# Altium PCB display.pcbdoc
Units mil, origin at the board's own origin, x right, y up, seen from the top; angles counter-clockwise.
Board outline 7440.31 x 2415 mil, 2 copper layers (Top Layer, Bottom Layer); 54 components, 78 nets, 200 pads, 151 vias.
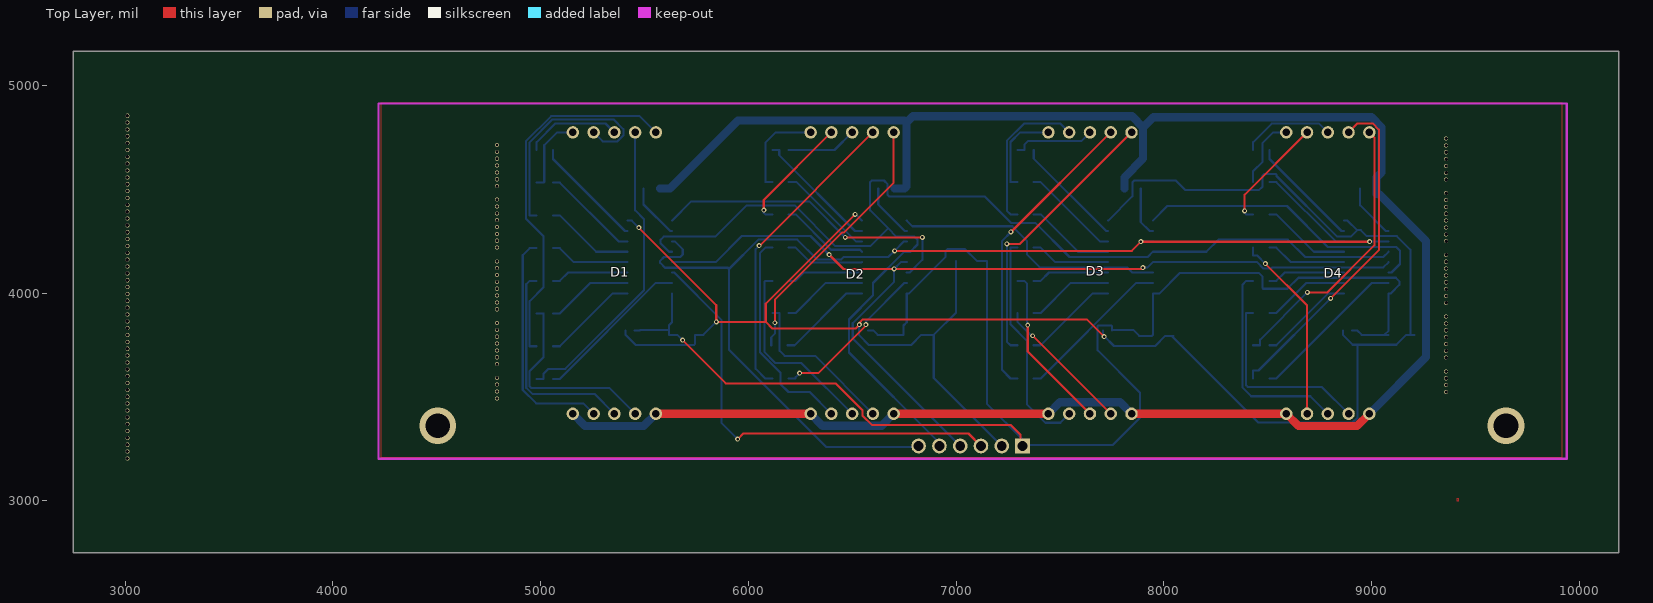
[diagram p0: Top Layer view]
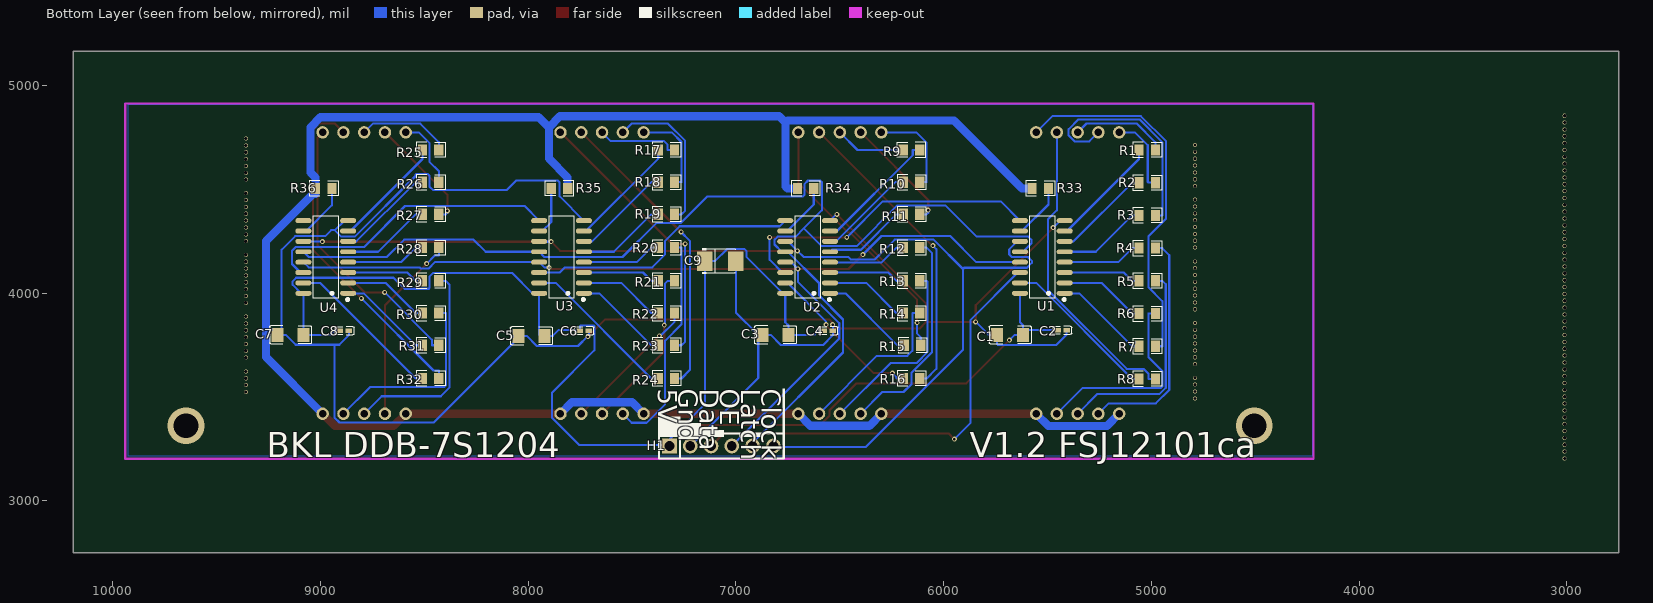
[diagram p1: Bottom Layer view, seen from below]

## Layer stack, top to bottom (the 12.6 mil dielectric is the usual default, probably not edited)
Top Layer: signal copper (thickness not stored)
Dielectric: dielectric 12.6, FR-4, Dk 4.8
Bottom Layer: signal copper (thickness not stored)

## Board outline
10190.31,2750 2750,2750 2750,5165 10190.31,5165

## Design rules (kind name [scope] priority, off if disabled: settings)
Clearance safeClearance [All] p1: gap=7 ignorepadtopadclearanceinfootprint=FALSE except(6: Track-Track Track-SMDPad SMDPad-SMDPad Track-THPad SMDPad-THPad THPad-THPad Track-Via SMDPad-Via THPad-Via Via-Via Track-Fill SMDPad-Fill THPad-Fill Via-Fill Fill-Fill Track-Region SMDPad-Region THPad-Region Via-Region Fill-Region Region-Region Track-Poly SMDPad-Poly THPad-Poly Via-Poly Fill-Poly Region-Poly Poly-Poly Track-Text SMDPad-Text THPad-Text Via-Text Fill-Text Region-Text Poly-Text Text-Text Track-Hole SMDPad-Hole THPad-Hole Via-Hole Fill-Hole Region-Hole Poly-Hole Text-Hole; 11.8: Track-Sheet SMDPad-Sheet THPad-Sheet Via-Sheet Fill-Sheet Region-Sheet Poly-Sheet Text-Sheet Sheet-Hole)
DiffPairsRouting differentialPair [All] p1: maxuncoupledlength=10 minlimit=6 maxlimit=50 mostfreqgap=6 toplayer_minwidth=5 toplayer_prefwidth=10 toplayer_maxwidth=100 bottomlayer_minwidth=5 bottomlayer_prefwidth=10 bottomlayer_maxwidth=100
PasteMaskExpansion pasteMaskExpansion [All] p1:
PlaneConnect innerPlane [All] p1: planeconnectstyle=Relief reliefexpansion=20 reliefentries=4 reliefconductorwidth=10 reliefairgap=10
PolygonConnect copperRegion [All] p1: connectstyle=Relief reliefentries=4 reliefconductorwidth=10 polygonreliefangle="90 Angle" airgapwidth=10
RoutingVias viaSize [All] p1: viastyle="Through Hole" holewidth=12.0078 minholewidth=11.811 maxholewidth=236.2204 width=24.0158 minwidth=19.685 maxwidth=393.7008
SolderMaskExpansion solderMaskExpansion [All] p1: useseparateexpansions=TRUE expansion=2 expansionbottom=2
Width trackWidth [All] p1: maxlimit=100 minlimit=5 preferedwidth=10
Width Vcc [All] p1: maxlimit=100 minlimit=24 preferedwidth=39

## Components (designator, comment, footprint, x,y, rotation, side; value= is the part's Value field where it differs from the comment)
C1 "CL31A476MPHNNNE" C1206 5679.84,3800 r0 bottom
C2 "CL05B104KO5NNNC" C0402_NEW 5429.84,3821.36 r180 bottom
C3 "CL31A476MPHNNNE" C1206 6809.84,3800 r0 bottom
C4 "CL05B104KO5NNNC" C0402_NEW 6554.84,3820 r180 bottom
C5 "CL31A476MPHNNNE" C1206 7984.84,3795 r0 bottom
C6 "CL05B104KO5NNNC" C0402_NEW 7729.84,3820 r180 bottom
C7 "CL31A476MPHNNNE" C1206 9144.84,3800 r0 bottom
C8 "CL05B104KO5NNNC" C0402_NEW 8884.84,3820 r180 bottom
C9 "CA45-B-10V-100uF-M" CAP-SMD_L3.5-W2.8-R-RD 7074.84,4155 r0 bottom
D1 "FJS12101" FJS12101 5354.84,4100 r0 top
D2 "FJS12101" FJS12101 6499.84,4100 r0 top
D3 "FJS12101" FJS12101 7644.84,4100 r0 top
D4 "FJS12101" FJS12101 8789.84,4100 r0 top
H1 "PZ254R-11-06P" HDR-TH_6P-P2.54-V_Z-211-0611-0021-001 7069.84,3265 r180 bottom
R1 "0805W8F1000T5E_C17408" R0805 5019.84,4690 r0 bottom
R2 "0805W8F1000T5E_C17408" R0805 5019.84,4532.52 r0 bottom
R3 "0805W8F1000T5E_C17408" R0805 5019.84,4375.04 r0 bottom
R4 "0805W8F1000T5E_C17408" R0805 5019.84,4217.56 r0 bottom
R5 "0805W8F1000T5E_C17408" R0805 5019.84,4060.08 r0 bottom
R6 "0805W8F1000T5E_C17408" R0805 5019.84,3902.6 r0 bottom
R7 "0805W8F1000T5E_C17408" R0805 5019.84,3745.12 r0 bottom
R8 "0805W8F1000T5E_C17408" R0805 5019.84,3587.64 r0 bottom
R9 "0805W8F1000T5E_C17408" R0805 6154.84,4690 r180 bottom
R10 "0805W8F1000T5E_C17408" R0805 6154.84,4535 r0 bottom
R11 "0805W8F1000T5E_C17408" R0805 6154.84,4380 r0 bottom
R12 "0805W8F1000T5E_C17408" R0805 6154.84,4220 r0 bottom
R13 "0805W8F1000T5E_C17408" R0805 6154.84,4060 r0 bottom
R14 "0805W8F1000T5E_C17408" R0805 6154.84,3905 r0 bottom
R15 "0805W8F1000T5E_C17408" R0805 6149.84,3750 r0 bottom
R16 "0805W8F1000T5E_C17408" R0805 6154.84,3590 r0 bottom
R17 "0805W8F1000T5E_C17408" R0805 7334.84,4690 r0 bottom
R18 "0805W8F1000T5E_C17408" R0805 7334.84,4535 r0 bottom
R19 "0805W8F1000T5E_C17408" R0805 7334.84,4380 r0 bottom
R20 "0805W8F1000T5E_C17408" R0805 7334.84,4220 r0 bottom
R21 "0805W8F1000T5E_C17408" R0805 7334.84,4060 r0 bottom
R22 "0805W8F1000T5E_C17408" R0805 7334.84,3905 r0 bottom
R23 "0805W8F1000T5E_C17408" R0805 7334.84,3750 r0 bottom
R24 "0805W8F1000T5E_C17408" R0805 7334.84,3590 r0 bottom
R25 "0805W8F1000T5E_C17408" R0805 8469.84,4690 r0 bottom
R26 "0805W8F1000T5E_C17408" R0805 8469.84,4535 r0 bottom
R27 "0805W8F1000T5E_C17408" R0805 8469.84,4380 r0 bottom
R28 "0805W8F1000T5E_C17408" R0805 8469.84,4220 r0 bottom
R29 "0805W8F1000T5E_C17408" R0805 8469.84,4060 r0 bottom
R30 "0805W8F1000T5E_C17408" R0805 8469.84,3905 r0 bottom
R31 "0805W8F1000T5E_C17408" R0805 8469.84,3750 r0 bottom
R32 "0805W8F1000T5E_C17408" R0805 8469.84,3590 r0 bottom
R33 "0805W8F1002T5E" R0805 5534.84,4505 r0 bottom
R34 "0805W8F1002T5E" R0805 6664.84,4505 r0 bottom
R35 "0805W8F1002T5E" R0805 7849.84,4505 r180 bottom
R36 "0805W8F1002T5E" R0805 8984.84,4505 r0 bottom
U1 "={Manufacturer Part}" SOIC-16_L9.9-W3.9-P1.27-LS6.0-BL 5524.84,4175 r90 bottom
U2 "={Manufacturer Part}" SOIC-16_L9.9-W3.9-P1.27-LS6.0-BL 6654.84,4175 r90 bottom
U3 "={Manufacturer Part}" SOIC-16_L9.9-W3.9-P1.27-LS6.0-BL 7839.84,4175 r90 bottom
U4 "={Manufacturer Part}" SOIC-16_L9.9-W3.9-P1.27-LS6.0-BL 8974.84,4175 r90 bottom

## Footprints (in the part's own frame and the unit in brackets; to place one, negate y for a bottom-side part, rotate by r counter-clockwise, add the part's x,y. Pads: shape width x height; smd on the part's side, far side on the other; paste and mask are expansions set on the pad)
C0402_NEW [mm]
  rect 0.79x0.54 smd: 1(-0.545,0) 2(0.545,0)
  silkscreen extent -1.17,-0.5 1.17,0.5
C1206 [mm]
  rect 1.485x1.728 smd: 1(-1.593,0) 2(1.593,0)
  silkscreen extent -2.56,-1.09 2.56,1.09
CAP-SMD_L3.5-W2.8-R-RD [mm]
  rect 1.9x2.376 smd: 1(1.899,0) 2(-1.899,0)
  silkscreen extent -1.83,-1.55 2.21,1.55
FJS12101 [mil]
  round 60 hole 36: 1(-200,-680) 2(-100,-680) 3(0,-680) 4(100,-680) 5(200,-680) 6(200,675) 7(100,675) 8(0,675) 9(-100,675) 10(-200,675)
HDR-TH_6P-P2.54-V_Z-211-0611-0021-001 [mil]
  rect 70.9x70.9 hole 47.2: 1(-250,0)
  round 70.9 hole 47.2: 2(-150,0) 3(-50,0) 4(50,0) 5(150,0) 6(250,0)
  silkscreen extent -300,-60 300,60
R0805 [mm]
  rect 1.133x1.377 smd: 1(-1,0) 2(1,0)
  silkscreen extent -1.76,-0.92 1.76,0.92
SOIC-16_L9.9-W3.9-P1.27-LS6.0-BL [mil]
  oval 23.7x77.6 smd: 1(-175,-107.7) 2(-125,-107.7) 3(-75,-107.7) 4(-25,-107.7) 5(25,-107.7) 6(75,-107.7) 7(125,-107.7) 8(175,-107.7) 9(175,107.7) 10(125,107.7) 11(75,107.7) 12(25,107.7) 13(-25,107.7) 14(-75,107.7) 15(-125,107.7) 16(-175,107.7)
  silkscreen extent -211,-111 198,60

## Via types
v1: diameter 19.68, hole 15.75, Top Layer to Bottom Layer, 121 vias
v2: diameter 24, hole 12, Top Layer to Bottom Layer, 28 vias
v3: diameter 177.17, hole 118.11, Top Layer to Bottom Layer, 2 vias

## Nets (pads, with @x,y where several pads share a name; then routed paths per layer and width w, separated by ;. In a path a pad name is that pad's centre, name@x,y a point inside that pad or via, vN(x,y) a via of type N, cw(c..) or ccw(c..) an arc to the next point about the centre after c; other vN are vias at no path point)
$1N2297: U1.9 U2.14 | length 1524.5
  Top Layer w10: v2(6466.54,4268.7) v2(6838.14,4268.7)
  Bottom Layer w10: U1.9 5725.34,4442.8 6292.44,4442.8 v2(6466.54,4268.7) ; U2.14 6776.84,4100 6838.14,4161.3 v2(6838.14,4268.7)
$1N2299: R8.2 U1.15 | length 764.8
  Bottom Layer w10: R8.2 5092.54,3587.6 5554.94,4050 U1.15
$1N2301: R33.1 U1.10 | length 267.3
  Bottom Layer w10: R33.1@5495.44,4505 5495.44,4427.7 5623.14,4300 U1.10
$1N2302: H1.4 U1.13 U2.13 U3.13 U4.13 | length 4830.4
  Top Layer w10: v2(6388.54,4186.6) 6457.94,4117.2 v2(6701.54,4117.2) 7893.74,4117.2 v2(7899.94,4123.5)
  Bottom Layer w10: U1.13 5842.94,4150 5968.84,4276 6299.24,4276 v2(6388.54,4186.6) ; U2.13 6734.24,4150 v2(6701.54,4117.2) 6701.54,4055 6502.64,3856.2 6502.64,3782.2 H1.4 ; v2(7899.94,4123.5) 7921.04,4123.5 U3.13 8449.44,4150 8479.94,4119.5 8518.24,4119.5 8523.74,4125 9057.54,4125 U4.13
$1N2303: H1.5 U1.12 U2.12 U3.12 U4.12 | length 5880.5
  Bottom Layer w10: U1.12 5617.74,4200 5577.94,4239.8 5577.94,4258.3 5592.64,4273 5841.34,4273 5991.44,4423.1 6222.64,4423.1 6418.74,4227 6587.64,4227 6673.24,4312.5 ; H1.5 6919.84,3279.6 6484.44,3715 6484.44,3874 6600.14,3989.7 6600.14,4049.5 6750.64,4200 U2.12 6779.44,4200 6814.34,4235 6814.34,4257.9 6799.24,4273 6712.74,4273 6673.24,4312.5 ; U4.12 9057.54,4175 8681.14,4175 8597.94,4258.2 8263.84,4258.2 8205.54,4200 U3.12 7922.54,4175 7546.04,4175 7381.84,4339.1 7264.64,4339.1 7136.94,4466.8 6677.34,4466.8 6670.84,4473.3 6670.84,4525.8 6653.34,4543.2 6594.94,4543.2 6586.34,4534.6 6586.34,4399.4 6673.24,4312.5
$1N2304: H1.3 U1.14 | length 2156.1
  Top Layer w10: v2(5948.24,3298) 5975.24,3325 7059.84,3325 H1.3 H1.3@7119.84,3255
  Bottom Layer w10: U1.14 5642.34,4100 5870.14,3872.2 5870.14,3376.1 v2(5948.24,3298)
$1N2305: H1.6 U1.11 U2.11 U3.11 U4.11 | length 5497.7
  Top Layer w10: v2(6704.14,4204.6) 7846.34,4204.6 v2(7889.94,4248.3) v2(8990.74,4248.3)
  Bottom Layer w10: U1.11 5645.44,4250 5684.14,4211.3 5684.14,4187 5672.14,4175 5594.04,4175 5575.14,4156 5575.14,4146.3 5598.44,4123 5901.14,4123 5907.04,4117.2 ; U2.11 6749.44,4250 v2(6704.14,4204.6) 6674.44,4175 6458.94,4175 6447.44,4163.5 6330.44,4163.5 6235.74,4258.2 6048.04,4258.2 5907.04,4117.2 ; H1.6@6809.84,3260 6375.14,3260 5907.04,3728.1 5907.04,4117.2 ; v2(7889.94,4248.3) 7945.84,4248.3 U3.11 ; v2(8990.74,4248.3) 8992.44,4250 U4.11
$1N6011: R7.2 U1.1 | length 463.5
  Bottom Layer w10: R7.2 5092.54,3745.1 5347.44,4000 U1.1
$1N6089: R3.2 U1.5 | length 430.4
  Bottom Layer w10: R3.2 5092.54,4375 5267.54,4200 U1.5
$1N6122: R6.2 U1.2 | length 419
  Bottom Layer w10: R6.2 5092.54,3902.6 5239.94,4050 U1.2
$1N6177: R5.2 U1.3 | length 374.4
  Bottom Layer w10: R5.2 5092.54,4060.1 5132.44,4100 U1.3
$1N6264: R4.2 U1.4 | length 385.9
  Bottom Layer w10: R4.2 5092.54,4217.6 5160.14,4150 U1.4
$1N6486: R2.2 U1.6 | length 474.9
  Bottom Layer w10: R2.2 5092.54,4532.5 5375.04,4250 U1.6
$1N6506: R1.2 U1.7 | length 544.7
  Bottom Layer w10: R1.2 5059.24,4646.8 5406.04,4300 U1.7
$1N40619: D1.7 R8.1 | length 1486.1
  Bottom Layer w10: R8.1@4980.44,3587.6 5013.74,3587.6 5013.74,3612.6 5037.64,3636.4 5118.54,3636.4 5497.44,4015.3 5497.44,4357.1 5454.84,4399.7 D1.7
$1N40652: D1.6 R7.1 | length 1791.3
  Bottom Layer w10: R7.1@4980.44,3745.1 4947.14,3745.1 4947.04,3745.2 4947.04,3961.6 5013.84,4028.4 5013.84,4275.4 4928.94,4360.3 4928.94,4731.7 5050.34,4853.1 5476.74,4853.1 D1.6
$1N40781: D1.9 R3.1 | length 1105.2
  Bottom Layer w10: R3.1@4980.44,4375 4947.14,4375 4947.04,4375.1 4947.04,4727 5056.74,4836.7 5351.54,4836.7 5398.54,4789.7 5398.54,4759.8 5370.24,4731.4 5298.44,4731.4 D1.9
$1N41012: D1.10 R2.1 | length 378.7
  Bottom Layer w10: R2.1@4980.44,4532.5 5013.74,4532.5 5017.34,4536.1 5017.34,4713.4 5079.04,4775 D1.10
$1N41044: D1.8 R1.1 | length 467.3
  Bottom Layer w10: R1.1@4980.44,4690 4980.44,4728.1 5070.04,4817.7 5312.14,4817.7 D1.8
$1N41338: D1.2 R4.1 | length 1118.9
  Bottom Layer w10: R4.1@4980.44,4217.6 4947.14,4217.6 4913.64,4184.1 4913.64,3534.5 4978.14,3470.1 5204.74,3470.1 D1.2
$1N41427: D1.4 R6.1 | length 974.5
  Bottom Layer w10: R6.1@4980.44,3902.6 5013.74,3902.6 5013.84,3902.5 5013.84,3692.7 4947.04,3625.8 4947.04,3551.3 4953.64,3544.7 5330.24,3544.7 D1.4
$1N41428: D1.3 R5.1 | length 1031.2
  Bottom Layer w10: R5.1@4980.44,4060.1 4947.14,4060.1 4930.74,4043.7 4930.74,3544.7 4959.74,3515.7 5259.14,3515.7 D1.3
$1N45593: R9.2 U2.7 | length 607.9
  Bottom Layer w10: R9.2@6115.44,4690 6148.74,4690 6148.74,4665 6513.74,4300 U2.7
$1N45594: R12.2 U2.4 | length 384.1
  Bottom Layer w10: R12.2 6227.54,4220 6300.24,4147.3 6544.44,4147.3 U2.4
$1N45595: R14.2 U2.2 | length 413
  Bottom Layer w10: R14.2 6227.54,3905 6372.54,4050 U2.2
$1N45596: R15.2 U2.1 | length 461.5
  Bottom Layer w10: R15.2 6222.54,3750 6472.54,4000 U2.1
$1N45597: R10.2 U2.6 | length 471
  Bottom Layer w10: R10.2 6232.84,4535 6517.84,4250 U2.6
$1N45598: R13.2 U2.3 | length 369.5
  Bottom Layer w10: R13.2 6227.54,4060 6267.54,4100 U2.3
$1N45599: R11.2 U2.5 | length 427.5
  Bottom Layer w10: R11.2 6227.54,4380 6397.84,4209.7 6537.44,4209.7 U2.5
$1N45600: R16.2 U2.15 | length 774
  Top Layer w10: v2(6246.54,3615.3) 6336.74,3615.3 6565.54,3844.1 v2(6565.54,3848.7)
  Bottom Layer w10: R16.2 6227.54,3590 6227.54,3596.3 v2(6246.54,3615.3) ; v2(6565.54,3848.7) 6565.54,3863.6 6751.84,4050 U2.15
$1N45601: D2.7 R16.1 | length 1472.8
  Top Layer w10: v2(6051.84,4229.3) 6054.14,4229.3 D2.7
  Bottom Layer w10: v2(6051.84,4229.3) 6035.44,4213 6035.44,3636.7 6082.14,3590 R16.1@6115.44,3590
$1N45602: D2.6 R15.1 | length 1274
  Top Layer w10: v2(6127.84,3858.2) 6127.84,3969.4 6450.14,4291.8 6458.44,4291.8 6699.84,4533.1 D2.6
  Bottom Layer w10: R15.1@6110.44,3750 6110.44,3788.1 6127.84,3805.5 v2(6127.84,3858.2)
$1N45603: D2.9 R11.1 | length 566.4
  Top Layer w10: v2(6074.24,4400) 6074.24,4449.4 D2.9
  Bottom Layer w10: v2(6074.24,4400) 6074.24,4387.9 6082.14,4380 R11.1@6115.44,4380
$1N45604: D2.10 R10.1 | length 462.2
  Bottom Layer w10: R10.1@6115.44,4535 6082.14,4535 6082.04,4535.1 6082.04,4725.5 6131.44,4775 D2.10
$1N45605: D2.8 R9.1 | length 340.8
  Bottom Layer w10: R9.1 6414.84,4690 D2.8
$1N45606: D2.4 R14.1 | length 790.9
  Bottom Layer w10: R14.1@6115.44,3905 6148.74,3905 6150.94,3902.8 6150.94,3722.6 6174.94,3698.6 6321.24,3698.6 D2.4
$1N45607: D2.3 R13.1 | length 923.6
  Bottom Layer w10: R13.1@6115.44,4060 6082.14,4060 6077.04,4054.9 6077.04,3718 6130.94,3664.1 6255.74,3664.1 D2.3
$1N45609: D2.2 R12.1 | length 1045.5
  Bottom Layer w10: R12.1@6115.44,4220 6082.14,4220 6057.04,4195 6057.04,3715.1 6154.84,3617.4 6154.84,3563 6193.14,3524.7 6295.14,3524.7 D2.2
$1N46574: R17.2 U3.7 | length 543.9
  Bottom Layer w10: R17.2 7374.24,4648.3 7722.54,4300 U3.7
$1N46575: R20.2 U3.4 | length 386.9
  Bottom Layer w10: R20.2 7407.54,4220 7477.54,4150 U3.4
$1N46576: R22.2 U3.2 | length 418
  Bottom Layer w10: R22.2 7407.54,3905 7552.54,4050 U3.2
$1N46577: R23.2 U3.1 | length 461.5
  Bottom Layer w10: R23.2 7407.54,3750 7657.54,4000 U3.1
$1N46578: R18.2 U3.6 | length 476
  Bottom Layer w10: R18.2 7407.54,4535 7692.54,4250 U3.6
$1N46579: R21.2 U3.3 | length 374.5
  Bottom Layer w10: R21.2 7407.54,4060 7447.54,4100 U3.3
$1N46580: R19.2 U3.5 | length 432.5
  Bottom Layer w10: R19.2 7407.54,4380 7587.54,4200 U3.5
$1N46581: R24.2 U3.15 | length 763.8
  Bottom Layer w10: R24.2 7407.54,3590 7867.54,4050 U3.15
$1N46582: D3.7 R24.1 | length 1452.2
  Top Layer w10: v2(7264.54,4295.3) 7744.24,4775 D3.7
  Bottom Layer w10: v2(7264.54,4295.3) 7221.54,4252.3 7221.54,3630.6 7262.14,3590 R24.1@7295.44,3590
$1N46583: D3.6 R23.1 | length 1351.3
  Top Layer w10: v2(7244.64,4238.2) 7308.04,4238.2 D3.6
  Bottom Layer w10: v2(7244.64,4238.2) 7244.64,3767.5 7262.14,3750 R23.1@7295.44,3750
$1N46584: D3.9 R19.1 | length 746.9
  Bottom Layer w10: R19.1@7295.44,4380 7262.14,4380 7244.34,4397.8 7244.34,4734.3 7326.94,4816.8 7503.04,4816.8 D3.9
$1N46585: D3.10 R18.1 | length 428.8
  Bottom Layer w10: R18.1@7295.44,4535 7262.14,4535 7262.04,4535.1 7262.04,4728.4 7308.64,4775 D3.10
$1N46586: D3.8 R17.1 | length 399.3
  Bottom Layer w10: R17.1@7295.44,4690 7328.74,4690 7328.74,4715 7346.04,4732.3 7602.14,4732.3 D3.8
$1N46587: D3.4 R22.1 | length 674.6
  Top Layer w10: v2(7369.24,3795.6) D3.4
  Bottom Layer w10: R22.1@7295.44,3905 7295.44,3863.5 7363.24,3795.6 v2(7369.24,3795.6)
$1N46588: D3.3 R21.1 | length 804.2
  Top Layer w10: v2(7345.24,3846.4) 7345.24,3719.6 D3.3
  Bottom Layer w10: R21.1@7295.44,4060 7328.74,4060 7340.84,4047.9 7340.84,3850.8 v2(7345.24,3846.4)
$1N46590: D3.2 R20.1 | length 1079
  Bottom Layer w10: R20.1@7295.44,4220 7262.14,4220 7262.04,4219.9 7262.04,3850.4 7340.84,3771.6 7340.84,3465.8 7429.94,3376.7 7501.54,3376.7 D3.2
$1N47559: R25.2 U4.7 | length 545
  Bottom Layer w10: R25.2 8509.24,4646.4 8855.64,4300 U4.7
$1N47560: R28.2 U4.4 | length 386.9
  Bottom Layer w10: R28.2 8542.54,4220 8612.54,4150 U4.4
$1N47561: R30.2 U4.2 | length 418
  Bottom Layer w10: R30.2 8542.54,3905 8687.54,4050 U4.2
$1N47562: R31.2 U4.1 | length 461.5
  Bottom Layer w10: R31.2 8542.54,3750 8792.54,4000 U4.1
$1N47563: R26.2 U4.6 | length 476
  Bottom Layer w10: R26.2 8542.54,4535 8827.54,4250 U4.6
$1N47564: R29.2 U4.3 | length 374.5
  Bottom Layer w10: R29.2 8542.54,4060 8582.54,4100 U4.3
$1N47565: R27.2 U4.5 | length 432.5
  Bottom Layer w10: R27.2 8542.54,4380 8722.54,4200 U4.5
$1N47566: R32.2 U4.15 | length 763.8
  Bottom Layer w10: R32.2 8542.54,3590 9002.54,4050 U4.15
$1N47567: D4.7 R32.1 | length 1640.5
  Top Layer w10: v2(8804.04,3975.9) 9035.94,4207.8 9035.94,4788.1 9005.64,4818.3 8933.14,4818.3 D4.7
  Bottom Layer w10: R32.1@8430.44,3590 8430.44,3628.1 8456.24,3628.1 v2(8804.04,3975.9)
$1N47568: D4.6 R31.1 | length 1353.1
  Top Layer w10: v2(8691.84,4004.3) 8788.24,4004.3 9014.44,4230.5 9014.44,4750.4 D4.6
  Bottom Layer w10: R31.1@8430.44,3750 8463.74,3750 8463.74,3776.2 v2(8691.84,4004.3)
$1N47569: D4.9 R27.1 | length 556.1
  Top Layer w10: v2(8389.24,4397.1) 8389.24,4474.4 D4.9
  Bottom Layer w10: v2(8389.24,4397.1) 8389.24,4387.9 8397.14,4380 R27.1@8430.44,4380
$1N47570: D4.10 R26.1 | length 343
  Bottom Layer w10: R26.1@8430.44,4535 8430.44,4589 8475.84,4634.3 8475.84,4724.1 8526.74,4775 D4.10
$1N47571: D4.8 R25.1 | length 451.7
  Bottom Layer w10: R25.1@8430.44,4690 8430.44,4728.1 8519.34,4817 8747.84,4817 D4.8
$1N47572: D4.4 R30.1 | length 931
  Bottom Layer w10: R30.1@8430.44,3905 8397.14,3905 8397.04,3904.9 8397.04,3556.8 8405.24,3548.6 8761.24,3548.6 D4.4
$1N47573: D4.3 R29.1 | length 1016.8
  Bottom Layer w10: R29.1@8430.44,4060 8397.14,4060 8379.74,4042.6 8379.74,3546 8421.44,3504.3 8705.54,3504.3 D4.3
$1N47575: D4.2 R28.1 | length 919
  Top Layer w10: v2(8489.44,4142.6) 8689.84,3942.3 D4.2
  Bottom Layer w10: R28.1@8430.44,4220 8430.44,4181.9 8450.24,4181.9 v2(8489.44,4142.6)
$1N47985: U2.9 U3.14 | length 1326.9
  Bottom Layer w10: U2.9 6789.54,4323 7270.64,4323 7340.84,4252.8 7340.84,4187.3 7403.14,4125 7823.34,4125 7848.34,4100 U3.14
$1N48013: U3.9 U4.14 | length 1444.4
  Bottom Layer w10: U3.9 8017.74,4420.2 8593.34,4420.2 8790.44,4223 9119.64,4223 9137.54,4205.1 9137.54,4140.8 9096.74,4100 U4.14
$1N52982: R34.1 U2.10 | length 267.3
  Bottom Layer w10: R34.1@6625.44,4505 6625.44,4427.7 6753.14,4300 U2.10
$1N53020: R36.1 U4.10 | length 269.6
  Bottom Layer w10: R36.1@8945.44,4505 8945.44,4423.7 9069.14,4300 U4.10
$1N56731: C1.1 C2.1 C3.1 C4.1 C5.1 C6.1 C7.1 C8.1 C9.1 H1.1 U1.16 U2.16 U3.16 U4.16 | length 7678.6
  Top Layer w10: v2(5683.34,3774.1) 5891.14,3566.3 6419.64,3566.3 6549.84,3436.1 6549.84,3411 6595.84,3365 7264.84,3365 7309.84,3320 7309.84,3260 H1.1@7319.84,3250
  Bottom Layer w10: C2.1 5477.94,3821.4 5479.04,3822.5 C1.1@5617.14,3822.5 ; U1.16 5632.54,3860.4 5617.14,3845 C1.1@5617.14,3822.5 ; v2(5683.34,3774.1) 5657.34,3800 C1.1 C1.1@5617.14,3822.5 ; C4.1 6602.94,3820 6622.94,3800 C3.1 6747.14,3845 6762.54,3860.4 U2.16 6773.94,4000 6948.44,4174.5 6948.44,4203.3 6958.04,4212.9 7043.34,4212.9 7101.24,4155 C9.1 7149.64,3466.7 7319.84,3296.5 H1.1@7319.84,3269.3 ; H1.1@7319.84,3250 H1.1@7319.84,3269.3 ; C6.1 C6.1@7751.34,3824.1 ; C8.1 8932.94,3820 8952.94,3800 C7.1@9062.04,3800 ; C7.1 C7.1@9062.04,3800 ; H1.1@7319.84,3269.3 7753.54,3269.3 7885.94,3401.7 7885.94,3521 7681.64,3725.4 7681.64,3841.3 7684.64,3844.3 7748.64,3844.3 7751.34,3841.6 C6.1@7751.34,3824.1 ; C6.1@7751.34,3824.1 7852.84,3824.1 7881.94,3795 C5.1 7942.24,3795 7947.54,3800.3 U3.16 7980.24,4000 8078.44,4098.2 8458.14,4098.2 8475.84,4080.5 8475.84,4024.7 8478.74,4021.8 8595.24,4021.8 8648.54,4075 9117.14,4075 9134.54,4057.6 9134.54,4040.7 9093.94,4000 U4.16 9082.54,3820.5 C7.1@9062.04,3800
$1N57025: R35.1 U3.10 | length 238.3
  Bottom Layer w10: R35.1 7889.24,4342.6 7931.84,4300 U3.10
GND: 
VCC: D1.1 D1.5 D2.1 D2.5 D3.1 D3.5 D4.1 D4.5 R33.2 R34.2 R35.2 R36.2 | length 10024.2
  Top Layer w39.4: D1.5 D2.1 ; D2.5 D3.1 ; D3.5 D4.1 8648.54,3361.3 8931.14,3361.3 D4.5
  Bottom Layer w39.4: D1.1 5213.54,3361.3 5496.14,3361.3 D1.5 ; R33.2 5622.24,4505 5949.74,4832.5 6751.04,4832.5 6762.04,4821.6 ; D2.1 6357.84,3362.1 6641.94,3362.1 D2.5 ; R34.2 6752.24,4505 6762.04,4514.8 6762.04,4821.6 ; D3.1 7500.64,3475.8 7789.04,3475.8 D3.5 ; R35.2@7810.44,4505 7810.44,4557.8 7900.84,4648.3 7900.84,4798.5 ; D4.5 9262.64,3692.8 9262.64,4251.7 9035.74,4478.6 9024.24,4478.6 R36.2 9024.24,4557.8 9048.54,4582.1 9048.54,4799.3 9000.04,4847.8 7950.24,4847.8 7900.84,4798.5 ; 6762.04,4821.6 6793.14,4852.8 7846.54,4852.8 7900.84,4798.5
pads on no net: C1.2 C2.2 C3.2 C4.2 C5.2 C6.2 C7.2 C8.2 C9.2 H1.2 U1.8 U2.8 U3.8 U4.8 U4.9
copper on no net: | length 9995.2
  Top Layer w10: v2(5472.84,4315.7) 5845.54,3943 v2(5845.54,3862.7) 6083.74,3862.7 ; v2(6513.84,4380.1) 6083.74,3950 6083.74,3862.7 ; v2(7712.74,3791.4) 7629.84,3874.2 6550.74,3874.2 6534.94,3858.5 v2(6534.94,3849.4) 6516.34,3830.8 6115.74,3830.8 6083.74,3862.7
  Bottom Layer w10: 5408.34,3821.4 5408.34,3799.8 5457.24,3750.9 5738.54,3750.9 5742.54,3755 5742.54,3800 5782.74,3800 v2(5845.54,3862.7) ; 5417.14,4350 5438.44,4350 v2(5472.84,4315.7) ; v2(6513.84,4380.1) 6517.04,4380.1 6547.14,4350 ; v2(6534.94,3849.4) 6533.34,3847.8 6533.34,3820 6533.34,3798.4 6581.04,3750.7 6783.04,3750.7 6832.34,3800 6872.54,3800 6892.64,3800 ; 7000.14,4155 7000.14,3907.5 6892.64,3800 ; 7219.84,3265 6892.64,3592.2 6892.64,3800 ; 7708.34,3820 7708.34,3798.4 v2@7714.04,3792.7 ; v2(7712.74,3791.4) v2@7714.04,3792.7 ; 7732.14,4350 7848.94,4466.8 7848.94,4533.4 7858.74,4543.2 8058.24,4543.2 8104.64,4496.8 8458.24,4496.8 8475.84,4514.3 8475.84,4567.1 8482.14,4573.4 8539.84,4573.4 8542.74,4570.5 8542.74,4565 8834.74,4273 8900.04,4273 8930.84,4303.9 ; 8047.54,3795 8037.54,3795 ; 8863.34,3820 8863.34,3798.4 8909.54,3752.2 8932.64,3752.2 ; 8867.14,4350 8884.74,4350 8930.84,4303.9 ; 9207.54,3800 9187.44,3800 ; v2@7714.04,3792.7 7760.64,3746.1 7958.44,3746.1 8007.34,3795 8037.54,3795 ; 8037.54,3795 8454.74,3377.8 8908.84,3377.8 8932.64,3401.6 8932.64,3752.2 ; 8930.84,4303.9 8948.44,4303.9 8977.34,4275 9122.04,4275 9187.44,4209.6 9187.44,3800 ; 8932.64,3752.2 9119.54,3752.2 9167.34,3800 9187.44,3800
  other v1: 3009.84,3205 3009.84,3238 3009.84,3271 3009.84,3304 3009.84,3337 3009.84,3370 3009.84,3403 3009.84,3436 3009.84,3469 4789.84,3494 3009.84,3502 9359.84,3525 4789.84,3527 3009.84,3535 9359.84,3558 4789.84,3560 3009.84,3568 9359.84,3591 4789.84,3593 3009.84,3601 9359.84,3624 3009.84,3634 4789.84,3659 3009.84,3667 9359.84,3690 4789.84,3692 3009.84,3700 9359.84,3723 4789.84,3725 3009.84,3733 9359.84,3756 4789.84,3758 3009.84,3766 9359.84,3789 4789.84,3791 3009.84,3799 9359.84,3822 4789.84,3824 3009.84,3832 9359.84,3855 4789.84,3857 3009.84,3865 9359.84,3888 3009.84,3898 4789.84,3923 3009.84,3931 9359.84,3954 4789.84,3956 3009.84,3964 9359.84,3987 4789.84,3989 3009.84,3997 9359.84,4020 4789.84,4022 3009.84,4030 9359.84,4053 4789.84,4055 3009.84,4063 9359.84,4086 4789.84,4088 3009.84,4096 9359.84,4119 4789.84,4121 3009.84,4129 9359.84,4152 4789.84,4154 3009.84,4162 9359.84,4185 3009.84,4195 4789.84,4220 3009.84,4228 9359.84,4251 4789.84,4253 3009.84,4261 9359.84,4284 4789.84,4286 3009.84,4294 9359.84,4317 4789.84,4319 3009.84,4327 9359.84,4350 4789.84,4352 3009.84,4360 9359.84,4383 4789.84,4385 3009.84,4393 9359.84,4416 4789.84,4418 3009.84,4426 9359.84,4449 4789.84,4451 3009.84,4459 9359.84,4482 3009.84,4492 4789.84,4516 4789.84,4517 3009.84,4525 9359.84,4547 9359.84,4548 4789.84,4549 3009.84,4558 9359.84,4580 4789.84,4582 3009.84,4591 9359.84,4613 4789.84,4615 3009.84,4624 9359.84,4646 4789.84,4648 3009.84,4657 9359.84,4679 4789.84,4681 3009.84,4690 9359.84,4712 4789.84,4714 3009.84,4723 9359.84,4745 3009.84,4756 3009.84,4789 3009.84,4822 3009.84,4855
  other v3: 4504.84,3362.48 9647.91,3362.48

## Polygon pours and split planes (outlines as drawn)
VCC on Top Layer (solid, remove dead copper): 9409.84,3000 9419.84,3000 9419.84,3010 9409.84,3010
no net on Bottom Layer (solid, remove dead copper, pour order 6): 4224.84,3215 9924.84,3215 9924.84,4910 4224.84,4910
no net on Top Layer (solid, remove dead copper, pour order 4): 4229.84,3210 9919.84,3210 9919.84,4915 4229.84,4915

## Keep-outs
Board Outline Layer:
  lines w10: 4219.84,3203.46 9940.31,3203.46 9940.31,4913.46 4219.84,4913.46 4219.84,3203.46

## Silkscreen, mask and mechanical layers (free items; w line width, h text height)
Bottom Silkscreen Layer:
  region: 6869.84,3308.7 6983.54,3308.7 6983.54,3320 6869.84,3320
  region: 7059.84,3310 7174.84,3310 7174.84,3340 7059.84,3340
  region: 7169.84,3310 7274.84,3310 7274.84,3375 7169.84,3375
  region: 7268.11,3310 7374.84,3310 7374.84,3404.92 7268.11,3404.92
  region: 6764.84,3310 6774.84,3310 6774.84,3540 6764.84,3540
  text "Clock" at 6874.84,3540 h90.55 r90
  text "Latch" at 6974.84,3540 h90.55 r90
  text "OE" at 7074.84,3540 h90.55 r90
  text "Data" at 7174.84,3540 h90.55 r90
  text "Gnd" at 7274.84,3540 h90.55 r90
  text "5V" at 7374.84,3540 h90.55 r90
  text "V1.2 FSJ12101ca" at 5874.84,3210 h120
  text "BKL DDB-7S1204" at 9259.84,3210 h120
